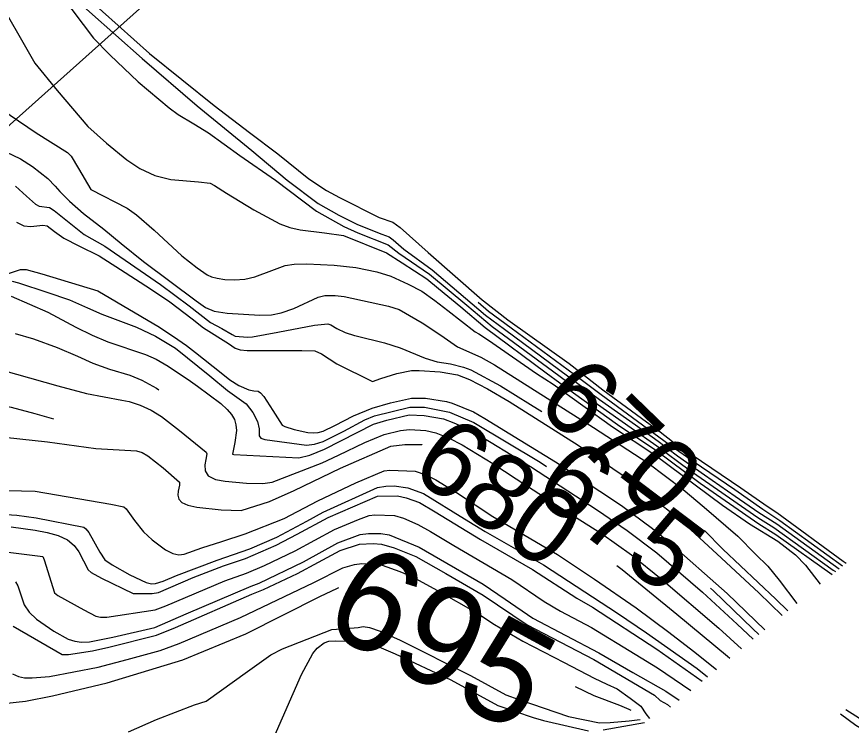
# Model space of a CAD drawing. Extents: x -291892836 to 2945206, y -477993085 to 1832792.
# Drawn here: x 1853835.7 to 1854108.7, y 545904.2 to 546136.2 of the extents above; entities that cross this region are included whole.
import ezdxf

# ---------------------------------------------------------------- set-up
doc = ezdxf.new("R2010")
doc.units = 0
for name, color, linetype in [('DT_X_Contour_Minor', 7, 'Continuous'), ('DT_X_Terrain_Ground_Line', 7, 'Continuous'), ('Level 63', 7, 'Continuous')]:
    doc.layers.add(name, color=color, linetype=linetype)

msp = doc.modelspace()

# ---------------------------------------------------------------- linework, layer by layer
at = {"layer": 'DT_X_Contour_Minor'}
for points in [[(1853838.51, 546156.54), (1853839, 546156.23), (1853859.49, 546137.71), (1853876.73, 546122.53), (1853894.68, 546106.99), (1853912.6, 546092.35), (1853924.12, 546082.7), (1853934.33, 546075.03), (1853941.08, 546071.21), (1853947.21, 546068.1), (1853955.09, 546064.96), (1853957.47, 546064.07), (1853958.78, 546063.1), (1853962.35, 546060.08), (1853971.57, 546053.34), (1853984.67, 546042.17)], [(1853840.87, 546158.47), (1853858.62, 546142.55), (1853879.15, 546124.17), (1853900.27, 546107.12), (1853911.87, 546098.21), (1853921.06, 546091.25), (1853931.23, 546083.06), (1853936.99, 546079.32), (1853941.31, 546076.93), (1853954.23, 546070.47), (1853958.72, 546068.89), (1853961.1, 546067.12), (1853970.31, 546058.95), (1853987.99, 546043.48), (1853988.36, 546043.18)], [(1853836.94, 546155.25), (1853839.98, 546153.37), (1853847.2, 546146.67), (1853850.37, 546143.07), (1853860.79, 546129.19), (1853866.09, 546123.71), (1853875.44, 546114.8), (1853885.56, 546106.34), (1853888.51, 546104.13), (1853893.59, 546101.12), (1853898.41, 546098.11), (1853908.7, 546090.76), (1853920.38, 546082.67), (1853933.7, 546072.46), (1853942.65, 546067.44), (1853947.22, 546065.41), (1853957.2, 546061.43), (1853960.67, 546058.73), (1853970.72, 546051.84), (1853982.91, 546041.68)], [(1853830.46, 546140.42), (1853836.35, 546130.1), (1853841.58, 546120.92), (1853848.9, 546111.96), (1853858.98, 546100.21), (1853865.06, 546094.71), (1853871.71, 546089.29), (1853875.98, 546086.44), (1853880.82, 546084.18), (1853886.09, 546082.89), (1853895.17, 546082.11), (1853898.92, 546081.68), (1853900.34, 546080.93), (1853904.28, 546078.43), (1853913.27, 546072.93), (1853921.79, 546068.33), (1853925.02, 546067.15), (1853928.4, 546066.4), (1853936.37, 546065.36), (1853942.58, 546064.53), (1853956.67, 546058.9), (1853961.75, 546055.62), (1853969.87, 546050.35), (1853973.65, 546047.23), (1853980.93, 546041.14)], [(1853827.59, 546107.87), (1853842.09, 546098.17), (1853852.24, 546091.7), (1853853.45, 546090.51), (1853855.94, 546086.51), (1853859.97, 546079.6), (1853871.77, 546073.47), (1853874.9, 546071.29), (1853880.62, 546066.33), (1853889.73, 546057.86), (1853894.7, 546053.91), (1853897.98, 546051.66), (1853899.37, 546051.01), (1853901.2, 546050.53), (1853903.79, 546050.18), (1853906.94, 546050.05), (1853910.3, 546050.29), (1853913.57, 546050.98), (1853919.13, 546053.04), (1853923.47, 546054.72), (1853926.45, 546055.17), (1853930.61, 546055.27), (1853939.51, 546054.86), (1853946.57, 546054.04), (1853953.53, 546052.65), (1853958.08, 546051.2), (1853963.78, 546048.59), (1853968.23, 546046.26), (1853972.44, 546043.29), (1853976.69, 546039.97)], [(1853829.72, 546093.02), (1853836.96, 546089.59), (1853840.82, 546087.09), (1853845.83, 546083.24), (1853848.29, 546080.64), (1853849.76, 546078.89), (1853852.95, 546075.73), (1853857.52, 546071.73), (1853864.18, 546066.65), (1853869.84, 546061.91), (1853877.18, 546056.08), (1853894.39, 546043.2), (1853897.48, 546040.94), (1853900.27, 546039.77), (1853904.51, 546039.12), (1853915.25, 546038.43), (1853919.04, 546038.59), (1853922.21, 546039.26), (1853926.33, 546040.67), (1853934.24, 546044.31), (1853936.51, 546044.86), (1853939.85, 546044.94), (1853942.83, 546044.55), (1853957.28, 546041.36), (1853960.76, 546040.29), (1853966.27, 546037.11)], [(1853835.27, 546080.7), (1853838.89, 546077.39), (1853841.86, 546074.74), (1853842.97, 546074.17), (1853846.42, 546073.67), (1853847.89, 546072.75), (1853857.78, 546064.84), (1853864.45, 546061), (1853882.69, 546048.49), (1853892.06, 546041.51), (1853899.03, 546036.09), (1853902.73, 546034.05), (1853906.11, 546032.14), (1853907.17, 546031.57), (1853911.15, 546031.28), (1853912.77, 546031.33), (1853921.06, 546032.88), (1853933.04, 546035.18), (1853937.5, 546035.57), (1853938.47, 546035.26), (1853940.39, 546034.07), (1853943.14, 546032.81), (1853946.21, 546031.83), (1853946.67, 546031.72)], [(1853835.57, 546068.92), (1853837.96, 546067.72), (1853840.27, 546067.46), (1853844.19, 546067.97), (1853845.65, 546067.66), (1853848.09, 546065.88), (1853851.05, 546063.65), (1853855.98, 546061.13), (1853862.69, 546057.85), (1853869.58, 546053.46), (1853879.43, 546047.05), (1853885.74, 546042.81), (1853893.07, 546037.23), (1853896.83, 546034.35), (1853904.97, 546029.15), (1853907.16, 546027.61), (1853908.76, 546027.11), (1853911.05, 546026.94), (1853928.96, 546026.85)], [(1853829.21, 546050.86), (1853836.86, 546053.44), (1853838.76, 546053.4), (1853843.91, 546051.94), (1853862.2, 546046.47), (1853882.37, 546034.48), (1853888.41, 546030.54), (1853891.26, 546028.53), (1853894.19, 546026.23), (1853902.51, 546019.57)], [(1853834.2, 546049.56), (1853836.3, 546049.06), (1853845.52, 546045.95), (1853852.97, 546043.53), (1853858.79, 546040.89), (1853863.47, 546038.8), (1853874.87, 546034.56), (1853881.13, 546031.58), (1853887.67, 546027.66), (1853898.8, 546018.55)], [(1853833.81, 546044.72), (1853845.86, 546039.41), (1853854.99, 546034.48), (1853860.33, 546031.87), (1853865.46, 546029.78), (1853877.83, 546025.55), (1853881.27, 546024.01), (1853885.17, 546021.79), (1853892.48, 546016.81)], [(1853982.91, 546041.68), (1853991.25, 546034.74), (1854013.01, 546018.71), (1854025.7, 546009.29), (1854036.68, 546001.59), (1854045.12, 545995.73), (1854055.71, 545987.78), (1854078.15, 545972.21), (1854083.38, 545968.94), (1854102.81, 545955.01), (1854103.56, 545954.49)], [(1853984.67, 546042.17), (1853989.06, 546038.43), (1853995.22, 546033.84), (1854016.3, 546018.3), (1854026.28, 546010.87), (1854038.08, 546002.52), (1854045.48, 545997.24), (1854051.81, 545992.41), (1854060.73, 545986.23), (1854070.72, 545979.24), (1854078.41, 545973.91), (1854084.37, 545970.1), (1854104.7, 545955.43)], [(1853986.58, 546042.69), (1853990.04, 546039.73), (1853997.43, 546034.26), (1854018.17, 546018.98), (1854026.86, 546012.45), (1854048.99, 545996.26), (1854056.93, 545990.71), (1854070.55, 545981.34), (1854079.8, 545974.92), (1854085.37, 545971.26), (1854105.82, 545956.35)], [(1853988.36, 546043.18), (1853996.31, 546036.98), (1854016.38, 546022.6), (1854027.45, 546014.04), (1854046.21, 546000.25), (1854050.22, 545997.12), (1854072.54, 545981.9), (1854081.19, 545975.94), (1854084.34, 545973.9), (1854106.07, 545957.9), (1854107, 545957.32)], [(1853976.69, 546039.97), (1853985.67, 546032.95), (1853986.84, 546032.37), (1853990.03, 546030.22), (1854005.69, 546019.31), (1854011.22, 546015.85), (1854030.58, 546001.89), (1854044.39, 545992.72), (1854066.59, 545976.27), (1854075.39, 545970.18), (1854084.66, 545964.44), (1854090.49, 545959.96), (1854093.7, 545956.67), (1854098.51, 545950.45), (1854098.56, 545950.39)], [(1853980.93, 546041.14), (1853988.94, 546034.42), (1854008.84, 546019.63), (1854017.83, 546013.04), (1854032.17, 546002.72), (1854044.75, 545994.23), (1854059.22, 545983.42), (1854078.45, 545970.2), (1854084.06, 545966.65), (1854102.43, 545953.57)], [(1853966.27, 546037.11), (1853968.29, 546035.93), (1853974.42, 546031.86), (1853979.92, 546028.06), (1853987.49, 546024.72), (1853991.97, 546022.19), (1854012.5, 546009.24), (1854024.32, 546001.68), (1854042.16, 545990.17), (1854053.75, 545981.36), (1854060.62, 545975.63), (1854071.58, 545966.15), (1854077.31, 545960.17), (1854081.43, 545956.34), (1854085.09, 545951.74), (1854090.85, 545944.07)], [(1853733.71, 546033.6), (1853739.14, 546033.25), (1853749.25, 546031.83), (1853756.38, 546032.25), (1853764.29, 546032.76), (1853774.9, 546032.65), (1853780.25, 546032.32), (1853785.96, 546031.46), (1853789.15, 546030.58), (1853800.82, 546026.47), (1853805.57, 546025.39), (1853826.2, 546021.73), (1853849.16, 546015.34), (1853858.54, 546012.84), (1853870.05, 546010.65)], [(1853835.16, 546032.47), (1853841.15, 546030.66), (1853848.86, 546027.91), (1853855.56, 546025.05), (1853860.53, 546022.7), (1853866.01, 546020.8), (1853872.66, 546018.78), (1853876.66, 546017.16), (1853881.37, 546014.56), (1853882.19, 546013.99)], [(1853946.67, 546031.72), (1853955.95, 546029.42), (1853961.17, 546027.79), (1853969.28, 546024.4), (1853973.21, 546023.14), (1853977.59, 546022.57), (1853981.89, 546021.48), (1853984.25, 546020.55), (1853993.96, 546015.31), (1854003.73, 546009.21), (1854007.46, 546006.87)], [(1853928.96, 546026.85), (1853933.16, 546026.82), (1853935.39, 546025.84), (1853940.44, 546022.57), (1853952.09, 546016.78), (1853954.84, 546017.73), (1853960, 546019.4), (1853964.85, 546020.29), (1853967.34, 546020.38), (1853974.19, 546019.93), (1853979.88, 546018.88), (1853983.75, 546017.41), (1853989.64, 546014.38), (1853996.73, 546010.17), (1854019.31, 545995.85), (1854036.38, 545984.41), (1854051.83, 545972.18), (1854066.21, 545958.92), (1854078.43, 545947.57), (1854086.09, 545940.16)], [(1853759.31, 546018.52), (1853765.97, 546018.1), (1853775.26, 546017.71), (1853779.33, 546017.01), (1853781.78, 546016.14), (1853786.5, 546015.27), (1853811.65, 546012.38), (1853823.52, 546010.57), (1853833.9, 546008.35), (1853841.62, 546006.3), (1853847.73, 546004.51)], [(1853898.8, 546018.55), (1853904.63, 546013.78), (1853910.74, 546009.45), (1853912.96, 546006.6), (1853914.46, 546003.65), (1853914.96, 546001.21), (1853915, 545998.99), (1853915.57, 545998.19), (1853916.87, 545997.73), (1853930.52, 545995.89), (1853933.04, 545996.21), (1853935.94, 545997.13), (1853942.66, 546000.5), (1853949.55, 546004.2), (1853952.68, 546005.48), (1853964.25, 546008.32), (1853969.08, 546008.34), (1853977.26, 546006.72), (1853985.27, 546003.36), (1854006.95, 545990.34), (1854009.03, 545988.96)], [(1853902.51, 546019.57), (1853905.39, 546017.27), (1853908.3, 546015.4), (1853911.56, 546013.97), (1853913.26, 546013.68), (1853914.65, 546013.56), (1853915.4, 546013.07), (1853916.47, 546011.86), (1853919.41, 546007.22), (1853922.46, 546002.49), (1853923.34, 546001.97), (1853926.4, 546001.08), (1853930.95, 546000.08), (1853932.76, 545999.89), (1853934.31, 546000.01), (1853935.89, 546000.49), (1853939.69, 546002.38), (1853945.87, 546005.45), (1853951.99, 546008.06), (1853958, 546009.72), (1853964.83, 546011.33), (1853969.45, 546011.32), (1853976.24, 546010.16), (1853978.18, 546009.67), (1853985.12, 546006.76), (1853988.77, 546004.68), (1854011.98, 545990.46), (1854033.56, 545976.1), (1854043.68, 545968.57), (1854048.57, 545964.56), (1854068.1, 545947.35), (1854080.36, 545935.46)], [(1853892.48, 546016.81), (1853894.84, 546015.2), (1853902.41, 546009.5), (1853904.54, 546007.62), (1853905.94, 546005.99), (1853906.87, 546004.33), (1853907.41, 546002.57), (1853907.57, 546000.68), (1853907, 545996.78), (1853906.3, 545992.97), (1853906.71, 545992.87), (1853927.94, 545991.8), (1853931.54, 545992.58), (1853936.34, 545994.57), (1853952.37, 546002.82), (1853956.71, 546004.1), (1853964.11, 546005.8), (1853969.02, 546005.64), (1853975.31, 546004.52), (1853978.63, 546003.26), (1853984.15, 546000.8), (1853990.86, 545996.75), (1854003.71, 545988.92), (1854025.65, 545974.59), (1854035.37, 545967.98), (1854045.06, 545960.62), (1854060.03, 545947.77), (1854071.33, 545937.34), (1854076.57, 545932.35)], [(1853870.05, 546010.65), (1853872.48, 546010.19), (1853876.09, 546008.99), (1853879.66, 546007.37), (1853883.04, 546005.3), (1853888.97, 546000.75), (1853897.68, 545993.58), (1853897.84, 545993.06), (1853897.5, 545991.2), (1853897.18, 545989.48), (1853897.28, 545987.54), (1853898.32, 545985.83), (1853900.66, 545984.71), (1853903.91, 545984.08), (1853910.84, 545983.5), (1853916.16, 545983.39), (1853919.19, 545983.82), (1853935.64, 545990.16), (1853940.92, 545992.66), (1853949.55, 545996.77), (1853955.92, 545999.42), (1853961.26, 546000.71), (1853964.18, 546000.99), (1853969.53, 546000.73), (1853972.77, 545999.94), (1853977.18, 545998.24), (1853981.41, 545996.05), (1853991.4, 545989.85), (1853999.06, 545984.89), (1854015.75, 545974.12), (1854026.97, 545967), (1854036.77, 545959.99), (1854046.46, 545952.13), (1854065.35, 545935.99), (1854072.8, 545929.26)], [(1853827.52, 545998.95), (1853845.75, 545996.96), (1853861.61, 545994.77), (1853874.83, 545994.01), (1853876.68, 545993.51), (1853878.6, 545992.43), (1853883.62, 545988.5), (1853888.88, 545983.84), (1853888.98, 545982.78), (1853888.45, 545980.81), (1853888.33, 545979.48), (1853888.66, 545978.19), (1853889.7, 545977.11), (1853891.62, 545976.25), (1853894.55, 545975.59), (1853902.58, 545974.74), (1853909.07, 545974.52), (1853918.39, 545977.49), (1853926.43, 545981.06), (1853941.65, 545988.4), (1853958.05, 545995.52), (1853962.59, 545996.13), (1853968.17, 545996.08), (1853968.27, 545996.04)], [(1853828.21, 545981.16), (1853841.73, 545980.83), (1853866.51, 545976.6), (1853870.7, 545975.7), (1853871.47, 545975.02), (1853874.21, 545971.27), (1853877.16, 545967.48), (1853879.95, 545964.94), (1853884.4, 545961.64), (1853886.71, 545960.46), (1853888.72, 545960.05), (1853890.46, 545960.23), (1853896.25, 545962.28), (1853902.8, 545964.35), (1853910.43, 545966.89), (1853923.14, 545971.86), (1853934.13, 545977.73), (1853946.6, 545983.58), (1853955.88, 545987.48), (1853957.73, 545987.77), (1853965.99, 545987.43), (1853969.54, 545986.19), (1853972.83, 545984.53), (1853979.57, 545980.41), (1853991.45, 545972.57), (1854012.55, 545960.11), (1854024.69, 545952.08), (1854038.31, 545942.65), (1854049.03, 545934.63), (1854057.12, 545928.47), (1854064.56, 545922.49)], [(1853828.62, 545973.37), (1853835.74, 545973.02), (1853842.06, 545972.15), (1853857.59, 545969.04), (1853858.32, 545968.52), (1853859.25, 545967.32), (1853862.91, 545960.83), (1853864.5, 545958.38), (1853866.9, 545956.78), (1853872.73, 545953.42), (1853878.02, 545950.94), (1853879.72, 545950.56), (1853881.1, 545950.61), (1853883.56, 545951.41), (1853887.93, 545953.23), (1853901.29, 545958.2), (1853911.99, 545962), (1853920.73, 545965.74), (1853930.59, 545971.07), (1853935.9, 545973.94), (1853953.66, 545982.03), (1853956.38, 545982.53), (1853959.17, 545982.54), (1853963.63, 545981.94), (1853968.72, 545980.07), (1853982.11, 545971.75), (1853988.87, 545967.66), (1854007.97, 545956.71), (1854032.23, 545940.87), (1854041.74, 545934.46), (1854058.23, 545922.74), (1854061.65, 545920.11)], [(1853833.87, 545969.16), (1853841.76, 545968.11), (1853845.66, 545967.36), (1853849.24, 545966.35), (1853852.24, 545964.94), (1853854.47, 545963.06), (1853856.03, 545960.98), (1853859.05, 545955.09), (1853860.05, 545954.21), (1853863.41, 545952.31), (1853873.81, 545947.35), (1853879.98, 545947.31), (1853882.1, 545947.71), (1853893.45, 545952.59), (1853903.34, 545956.39), (1853910.51, 545958.84), (1853920.59, 545963.18), (1853927.38, 545966.73), (1853937.57, 545972.23), (1853953.71, 545979.21), (1853960.24, 545979.31), (1853963.13, 545978.65), (1853967.42, 545977.09), (1853972.55, 545974.09), (1853987.43, 545965.04), (1854004.41, 545955.23), (1854018.92, 545945.86), (1854023.99, 545942.89), (1854045.11, 545929.17), (1854059.9, 545918.67)], [(1853818.89, 545962.58), (1853844.25, 545959.46), (1853844.7, 545958.31), (1853848.02, 545947.52), (1853849.15, 545946.73), (1853857.61, 545942.01), (1853861.52, 545939.97), (1853863.09, 545939.57), (1853865.18, 545939.61), (1853880.99, 545942.04), (1853884.47, 545943.25), (1853903.76, 545951.52), (1853910.8, 545954.03), (1853916.78, 545956.49), (1853926.8, 545961.32), (1853939.62, 545968.24), (1853947.51, 545971.55), (1853950.94, 545972.87), (1853952.78, 545973.14), (1853959.3, 545972.9), (1853962.17, 545971.96), (1853966.93, 545969.97), (1853971.02, 545967.66), (1853978.64, 545963.05), (1853997.6, 545951.96), (1854008.27, 545944.71), (1854013.58, 545941.61), (1854023.74, 545936.18), (1854037.97, 545927.46), (1854045.34, 545923), (1854056.19, 545915.63)], [(1854060.73, 545967.93), (1854066.64, 545961.9), (1854083.97, 545945.52), (1854087.95, 545941.69)], [(1853835.3, 545951.16), (1853836.04, 545949.88), (1853838.15, 545943.64), (1853839.76, 545941.2), (1853842.13, 545938.9), (1853847.79, 545935.03), (1853852.53, 545932.42), (1853854.64, 545931.69), (1853856.84, 545931.41), (1853859.44, 545931.56), (1853867.13, 545933.04), (1853880.87, 545936.25), (1853891.14, 545940.67), (1853912.34, 545949.71), (1853914.97, 545950.69), (1853929.44, 545957.67), (1853940.73, 545963.9), (1853948.04, 545966.61), (1853950.77, 545967.01), (1853954.81, 545966.94), (1853957.53, 545966.56), (1853967.35, 545962.56), (1853988.24, 545950.35), (1853995.46, 545945.45), (1854004.51, 545939.29), (1854026.14, 545927.91), (1854037.27, 545921.45), (1854048.01, 545915.32), (1854052.34, 545912.47)], [(1853834.52, 545936.63), (1853850.51, 545927.41), (1853852.62, 545927.38), (1853860.51, 545928.52), (1853865.78, 545929.73), (1853881.39, 545933.66), (1853887.59, 545936.23), (1853912.61, 545947.13), (1853916.43, 545948.68), (1853927.5, 545953.88), (1853934.39, 545957.62), (1853941.44, 545961.42), (1853947.86, 545963.45), (1853952.25, 545963.76), (1853955.04, 545963.49), (1853959.15, 545962.28), (1853966.24, 545959.44), (1853976.04, 545953.91), (1853988.27, 545946.75), (1854002.66, 545937.13), (1854024.44, 545925.77), (1854044.3, 545914.01), (1854046.18, 545912.35), (1854048.56, 545910.96), (1854049.55, 545910.18)], [(1853834.35, 545920.99), (1853836.27, 545920.15), (1853838.25, 545919.75), (1853840.71, 545919.68), (1853846.4, 545920.21), (1853862.28, 545923.24), (1853871.81, 545925.69), (1853882.58, 545928.65), (1853888.83, 545930.94), (1853908.89, 545939.44), (1853932.84, 545950.98), (1853942.33, 545955.76), (1853946.18, 545956.88), (1853948.53, 545957.11), (1853955.25, 545956.62), (1853961.06, 545954.53), (1853964.96, 545952.86), (1853973.16, 545948.4), (1853986.56, 545940.84), (1853991.97, 545937.22), (1854001.3, 545931.79), (1854014.76, 545924.7), (1854024.63, 545919.6), (1854028.77, 545917.61), (1854032.06, 545916.08), (1854036.39, 545913.03), (1854039.8, 545910.41), (1854041.53, 545907.97), (1854042.7, 545906.39)], [(1854031.96, 545956.53), (1854033.76, 545955.24), (1854051.61, 545940.56), (1854068.15, 545926.85), (1854068.99, 545926.13)], [(1853831.43, 545911.37), (1853838.52, 545912.12), (1853847.42, 545913.8), (1853865.28, 545918.15), (1853890.07, 545925.66), (1853910.65, 545934.1), (1853935.07, 545946.46), (1853940.35, 545948.99), (1853941.1, 545949.27)], [(1854062.64, 545949.06), (1854063.63, 545948.2), (1854076.44, 545935.81), (1854078.44, 545933.89)], [(1853872.29, 545902.09), (1853881.41, 545906.08), (1853893.81, 545910.85), (1853897.68, 545912.08), (1853911.12, 545921.79), (1853918.8, 545927.22), (1853922.64, 545929.2), (1853938.71, 545935.6), (1853943.33, 545935.91), (1853947.35, 545936.21), (1853949.06, 545936.56), (1853951.04, 545936.25), (1853954.54, 545935), (1853961.15, 545932.08), (1853984.11, 545920.51), (1853995.64, 545914.21), (1853999.9, 545912.59), (1854016.14, 545907.11), (1854026.36, 545904.97), (1854029.86, 545905.11), (1854036.07, 545905.71), (1854038.64, 545906.01), (1854039.6, 545906.06)], [(1853919.95, 545900.37), (1853928.84, 545920.82), (1853932.56, 545927.68), (1853933.94, 545929.4), (1853936.29, 545931.16), (1853937.73, 545931.76), (1853939.92, 545931.89), (1853950.27, 545931.54), (1853959.45, 545927.59), (1853977.67, 545919.05), (1853993.04, 545910.71), (1854004.67, 545906.75), (1854007.96, 545905.73), (1854022.69, 545902.37)], [(1854018.33, 545916.92), (1854024.46, 545913.98), (1854032.83, 545910.77), (1854035.92, 545909.49), (1854036.62, 545909.18)], [(1854105.18, 545907.91), (1854110.14, 545904.26), (1854112.07, 545903.11), (1854117.19, 545901.36), (1854130.13, 545898), (1854135.89, 545896.5), (1854146.96, 545894), (1854149.04, 545893.22), (1854150.2, 545892.97)], [(1854106.96, 545909.37), (1854113.47, 545905.23), (1854117.3, 545903.71), (1854130.32, 545899.99), (1854135.74, 545898.37), (1854147.27, 545895.64), (1854149.6, 545894.67), (1854150.64, 545894.4)], [(1854027.55, 545902.68), (1854041, 545905.06)]]:
    msp.add_lwpolyline(points, dxfattribs=at)
at = {"layer": 'Level 63'}
msp.add_line((1854490.96, 546689.08), (1852771.58, 545150.8), dxfattribs=at)

# ---------------------------------------------------------------- texts
at = {"layer": 'DT_X_Terrain_Ground_Line'}
for s, height, rotation, p in [('670', 25, 315.8659, (1854004.83, 546009.12)), ('680', 25, 324.5118, (1853963.61, 545986.63)), ('675', 25, 322.8961, (1854003.59, 545979.83)), ('695', 33, 331.479, (1853934.57, 545936.3))]:
    msp.add_text(s, height=height, rotation=rotation, dxfattribs=at).set_placement(p)

doc.saveas('drawing.dxf')
